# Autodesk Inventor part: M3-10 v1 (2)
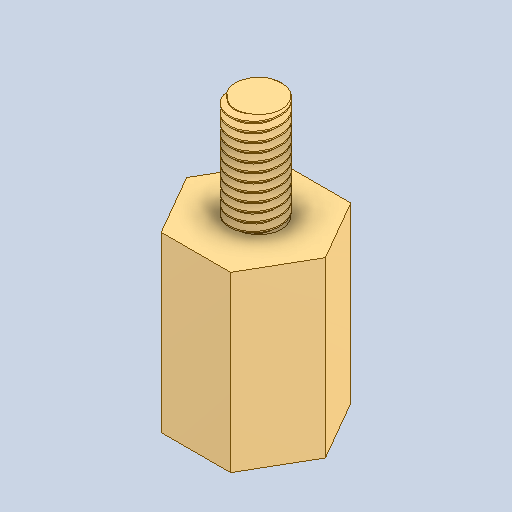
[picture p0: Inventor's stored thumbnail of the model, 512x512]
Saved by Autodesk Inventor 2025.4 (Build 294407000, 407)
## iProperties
Created: 2026-09
Part Number: M3-10 v1 (2)
Material: Generic
Document SubType Name: Modeling
Designer: AdminForWorker
Density: 1 g/cm^3
Appearance: Default
Title: M3-10 v1 (2)
Author: AdminForWorker
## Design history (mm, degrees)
feature "Body1"
body "Solid1"
